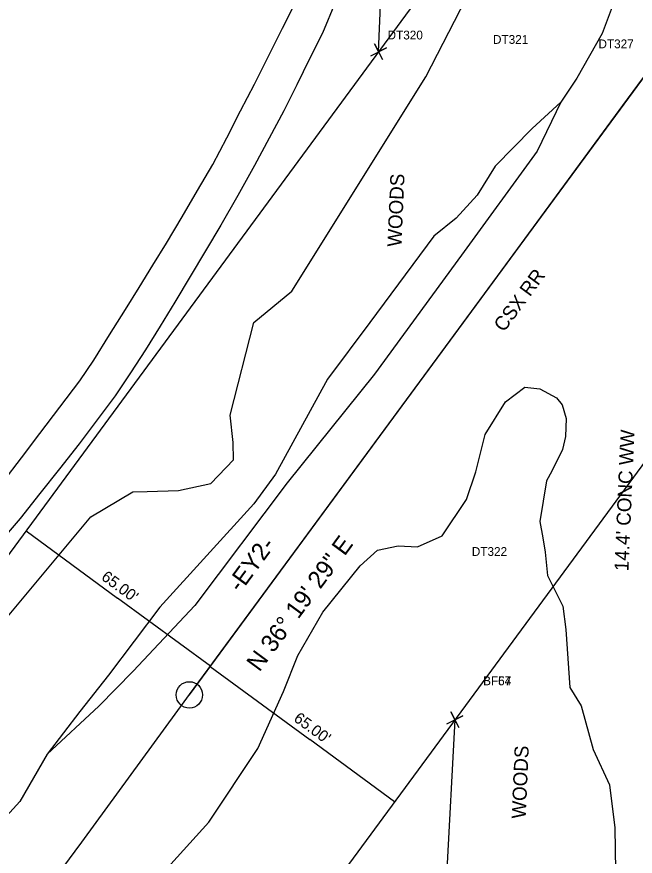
# Model space of a CAD drawing. Extents: x 2262665 to 2270527, y 505476 to 514960.
# Drawn here: x 2266066.3 to 2266242.1, y 510262.5 to 510501.2 of the extents above; entities that cross this region are included whole.
import ezdxf

# ---------------------------------------------------------------- set-up
doc = ezdxf.new("R2010")
doc.units = 0
for name, color, linetype in [('Exist Horizontal Alignment', 7, 'Continuous'), ('Exist Horizontal Alignment Direction Label', 7, 'Continuous'), ('Exist Property Corner CELL', 7, 'Continuous'), ('Exist Property Corner Cogo Number', 7, 'Continuous'), ('Exist Railroads Standard Gauge', 7, 'Continuous'), ('Exist Railroads Standard Gauge Text', 7, 'Continuous'), ('Exist Right of Way Line', 7, 'Continuous'), ('Exist Right of Way Width CELL', 7, 'Continuous'), ('Exist Roads Soil', 7, 'Continuous'), ('Exist Structure Major Bridge WW Text', 7, 'Continuous'), ('Exist Vegetation Hedge Row', 7, 'Continuous'), ('Exist Vegetation Woods Line', 7, 'Continuous'), ('Exist Vegetation Woods Line Text', 7, 'Continuous')]:
    doc.layers.add(name, color=color, linetype=linetype)

msp = doc.modelspace()

# ---------------------------------------------------------------- linework, layer by layer
at = {"layer": 'Exist Horizontal Alignment'}
msp.add_line((2266115.37, 510308.34), (2266484.61, 510810.55), dxfattribs=at)
msp.add_circle((2266115.37, 510308.34), 3.75, dxfattribs=at)
at = {"layer": 'Exist Property Corner CELL'}
for p, q in [((2266169.17, 510491.24), (2266169.17, 510491.24)), ((2266190.84, 510301.26), (2266190.84, 510301.26))]:
    msp.add_line(p, q, dxfattribs=at)
for points in [[(2266166.93, 510490.12), (2266171.4, 510492.37), (2266169.17, 510491.24), (2266168.04, 510493.48), (2266170.29, 510489.01)], [(2266188.6, 510300.13), (2266193.07, 510302.38), (2266190.84, 510301.26), (2266189.71, 510303.49), (2266191.96, 510299.02)]]:
    msp.add_lwpolyline(points, dxfattribs=at)
at = {"layer": 'Exist Railroads Standard Gauge'}
msp.add_lwpolyline([(2266050.13, 510219.7), (2266084.79, 510266.49), (2266115.4, 510308.45), (2266145.35, 510349.15), (2266177.14, 510392.25), (2266205.29, 510430.68), (2266238.56, 510475.95), (2266285.01, 510539.01), (2266316.09, 510581.21), (2266370.93, 510656.02), (2266407.4, 510705.52), (2266453.51, 510768.36), (2266484.6, 510810.49), (2266484.6, 510810.49), (2266581.19, 510941.59), (2266616.47, 510989.01)], dxfattribs=at)
at = {"layer": 'Exist Right of Way Line'}
for p, q in [((2266169.17, 510491.24), (2266223.4, 511803.97)), ((2265436.99, 509495.4), (2266823.18, 511380.77)), ((2266927.92, 511303.77), (2265541.79, 509418.49)), ((2266190.84, 510301.26), (2266182.85, 510150.01))]:
    msp.add_line(p, q, dxfattribs=at)
at = {"layer": 'Exist Right of Way Width CELL'}
for p, q in [((2266068.97, 510354.96), (2266094.91, 510335.89)), ((2266121.34, 510316.46), (2266094.91, 510335.89)), ((2266121.33, 510316.45), (2266149.61, 510295.65)), ((2266173.7, 510277.94), (2266149.61, 510295.65))]:
    msp.add_line(p, q, dxfattribs=at)
at = {"layer": 'Exist Roads Soil'}
for points in [[(2266156.93, 510505.49), (2266153.24, 510496.57), (2266149.56, 510489.21), (2266145.88, 510481.86), (2266142.21, 510474.5), (2266138.07, 510466.69), (2266133.93, 510458.89), (2266129.13, 510450.39), (2266124.34, 510441.9), (2266119.97, 510434.61), (2266115.6, 510427.32), (2266111.23, 510420.02), (2266107.08, 510413.24), (2266102.92, 510406.47), (2266098.62, 510399.91), (2266094.32, 510393.35), (2266089.16, 510386.55), (2266084, 510379.75), (2266078.42, 510372.68), (2266072.84, 510365.61), (2266067.26, 510358.54), (2266059.26, 510349.17)], [(2266062.47, 510368.91), (2266067.68, 510375.8), (2266072.89, 510382.68), (2266078.56, 510390.16), (2266084.23, 510397.64), (2266088.18, 510403.54), (2266092.71, 510410.75), (2266097.23, 510417.96), (2266101.13, 510424.25), (2266105.02, 510430.55), (2266108.91, 510436.84), (2266113.29, 510444.29), (2266117.68, 510451.75), (2266122.06, 510459.2), (2266125.99, 510466.82), (2266129.91, 510474.44), (2266133.84, 510482.06), (2266137.83, 510490), (2266141.83, 510497.94), (2266145.82, 510505.88)]]:
    msp.add_lwpolyline(points, dxfattribs=at)
at = {"layer": 'Exist Vegetation Hedge Row'}
msp.add_lwpolyline([(2266220.99, 510476.93), (2266214.21, 510462.99), (2266192.75, 510433.41), (2266167.99, 510399.59), (2266143.2, 510368.64), (2266116.89, 510333.8), (2266099.39, 510315.06), (2266089.62, 510305.17), (2266074.99, 510291.51)], dxfattribs=at)
at = {"layer": 'Exist Vegetation Woods Line'}
for points in [[(2266047.76, 510310.15), (2266047.62, 510310.56), (2266063.24, 510329.99), (2266087.39, 510358.98), (2266099.32, 510366.13), (2266103.38, 510366.21), (2266112.26, 510366.44), (2266121.45, 510368.44), (2266127.93, 510375.19), (2266127.79, 510380.16), (2266127.01, 510387.89), (2266133.66, 510414.3), (2266144.54, 510423.2), (2266182.61, 510484.09), (2266200.58, 510519.21), (2266205.61, 510545.92), (2266207.01, 510564.26), (2266208.73, 510590.97), (2266208.96, 510604.77), (2266214.78, 510659.48), (2266220.62, 510722.6), (2266223.2, 510773.11), (2266222.02, 510787.93)], [(2266237.88, 510510.2), (2266232.7, 510496.41), (2266225.52, 510483.72), (2266220.99, 510476.93), (2266212.79, 510469.43), (2266202.33, 510458.69), (2266197.21, 510450.45), (2266191.21, 510443.95), (2266184.88, 510438.83), (2266166.68, 510414.24), (2266154.68, 510398.09), (2266139.86, 510371.09), (2266133.68, 510362.65), (2266106.94, 510333.3), (2266092.38, 510313.92), (2266084.21, 510303.57), (2266074.99, 510291.51), (2266067.13, 510277.98), (2266059.44, 510269.53), (2266055.04, 510264.23), (2266054.91, 510264.38)], [(2266110.06, 510260.22), (2266120.92, 510272.12), (2266134.86, 510293.11), (2266142.14, 510309.31), (2266146.16, 510319.52), (2266153.3, 510331.83), (2266163.97, 510345.02), (2266168.89, 510349.51), (2266174.7, 510350.7), (2266180.23, 510350.49), (2266187.2, 510353.59), (2266194.15, 510363.9), (2266196.83, 510371.75), (2266199.46, 510382.39), (2266205.2, 510391.68), (2266210.76, 510395.82), (2266215, 510395.43), (2266219.78, 510392.81), (2266221.32, 510390.79), (2266222.46, 510386.93), (2266222.29, 510381.85), (2266221.42, 510378.1), (2266218.38, 510372.01), (2266216.92, 510369.22), (2266215.02, 510357.62), (2266215.87, 510353.04), (2266216.47, 510348.93), (2266217.13, 510342.27), (2266221.49, 510333.54), (2266222.38, 510326.93), (2266223.48, 510310.48), (2266226.75, 510305.22), (2266230.17, 510292.76), (2266234.79, 510282.73), (2266236.28, 510270.51), (2266236.51, 510258.34)]]:
    msp.add_lwpolyline(points, dxfattribs=at)

# ---------------------------------------------------------------- texts
at = {"layer": 'Exist Horizontal Alignment Direction Label'}
for s, p in [('N 36%%d 19\' 29" E', (2266135.27, 510314.67)), ('-EY2-', (2266129.84, 510337.21))]:
    msp.add_text(s, height=5, rotation=53.6754, dxfattribs=at).set_placement(p)
at = {"layer": 'Exist Property Corner Cogo Number'}
for s, p in [('DT320', (2266171.71, 510494.76)), ('DT321', (2266201.68, 510493.51)), ('DT327', (2266231.66, 510492.25)), ('DT322', (2266195.66, 510347.87)), ('BF67', (2266198.88, 510311.09)), ('BF54', (2266198.87, 510311.08))]:
    msp.add_text(s, height=2.5, dxfattribs=at).set_placement(p)
at = {"layer": 'Exist Railroads Standard Gauge Text'}
msp.add_text('CSX RR', height=4, rotation=53.7747, dxfattribs=at).set_placement((2266204.8, 510411.32))
at = {"layer": 'Exist Right of Way Width CELL'}
for p in [(2266090.09, 510341.32), (2266144.78, 510301.09)]:
    msp.add_text("65.00'", height=3.2, rotation=323.6754, dxfattribs=at).set_placement(p)
at = {"layer": 'Exist Structure Major Bridge WW Text'}
msp.add_text("14.4' CONC WW", height=4, rotation=87.4803, dxfattribs=at).set_placement((2266240.18, 510343.46))
at = {"layer": 'Exist Vegetation Woods Line Text'}
for p in [(2266175.63, 510435.71), (2266210.96, 510273.05)]:
    msp.add_text('WOODS', height=4, rotation=87.4803, dxfattribs=at).set_placement(p)

doc.saveas('drawing.dxf')
